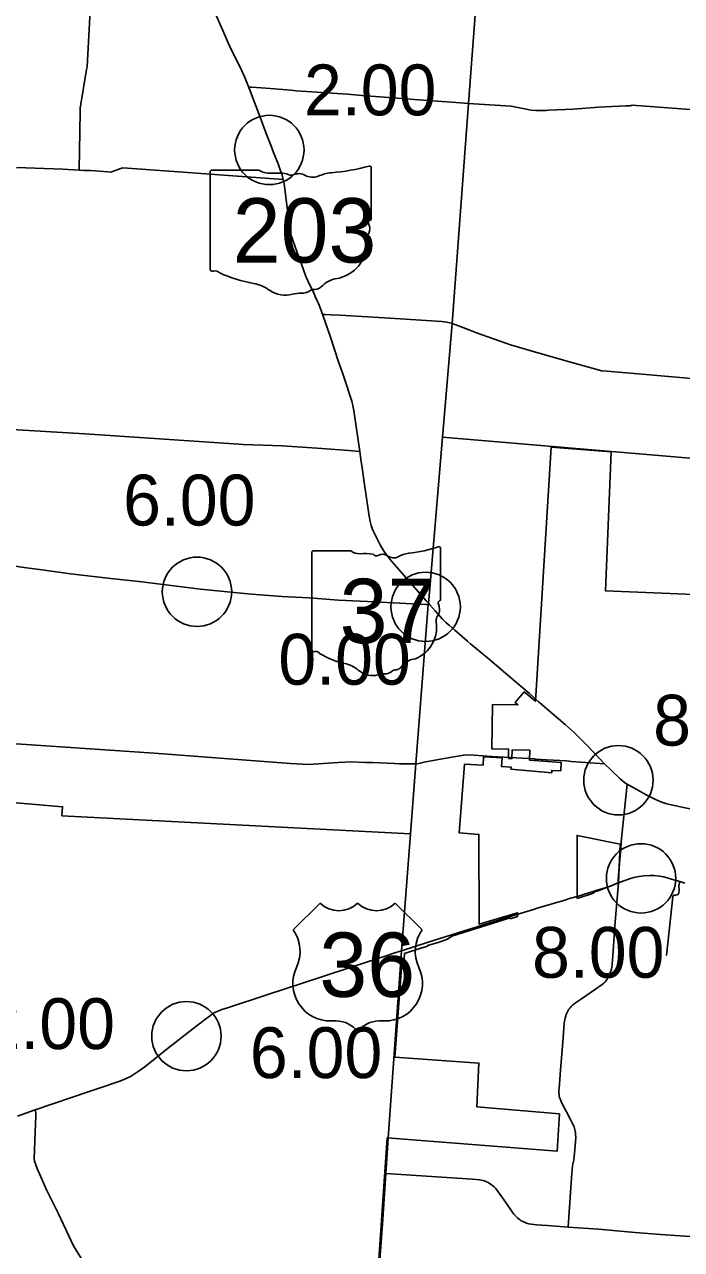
# Model space of a CAD drawing. Extents: x 1729596 to 1934326, y 644115 to 911751.
# Drawn here: x 1785492 to 1799698, y 831686 to 858198 of the extents above; entities that cross this region are included whole.
import ezdxf

# ---------------------------------------------------------------- set-up
doc = ezdxf.new("R2010")
doc.units = 0
for name, color, linetype in [('Default', 7, 'Continuous'), ('GM_X_City_Street', 7, 'Continuous'), ('GM_X_Corporation', 7, 'Continuous'), ('GM_X_County_Road', 7, 'Continuous'), ('GM_X_State_Route', 7, 'Continuous'), ('GM_X_State_Shield', 7, 'Continuous'), ('GM_X_Township', 7, 'Continuous'), ('GM_X_Township_Road', 7, 'Continuous'), ('GM_X_US_Route', 7, 'Continuous'), ('GM_X_US_Shield', 7, 'Continuous')]:
    doc.layers.add(name, color=color, linetype=linetype)

msp = doc.modelspace()

# ---------------------------------------------------------------- linework, layer by layer
at = {"layer": 'Default'}
for centre in [(1790786, 855482), (1789222, 845920), (1794166, 845595), (1798335, 841842), (1798823, 839718), (1788994, 836303)]:
    msp.add_circle(centre, 750, dxfattribs=at)
at = {"layer": 'GM_X_City_Street'}
for points in [[(1797209, 842260), (1797313, 842248), (1798035, 842200)], [(1798391, 840480), (1798393, 840510), (1798525, 841754)], [(1797247, 832172), (1797308, 833027), (1797327, 833333), (1797341, 833506), (1797367, 833630), (1797385, 833772), (1797411, 834102), (1797410, 834129), (1797409, 834165), (1797403, 834211), (1797397, 834244), (1797390, 834277), (1797383, 834312), (1797374, 834341), (1797357, 834387), (1797336, 834430), (1797307, 834485), (1797208, 834668), (1797135, 834807), (1797094, 834887), (1797073, 834944), (1797063, 834978), (1797055, 835013), (1797051, 835044), (1797048, 835076), (1797048, 835124), (1797051, 835173), (1797082, 835564), (1797140, 836270), (1797162, 836583), (1797170, 836630), (1797176, 836667), (1797183, 836695), (1797196, 836742), (1797207, 836777), (1797219, 836804), (1797233, 836833), (1797248, 836861), (1797265, 836886), (1797288, 836914), (1797313, 836944), (1797338, 836971), (1797374, 837003), (1797407, 837026), (1797534, 837113), (1797816, 837304), (1797982, 837420), (1798018, 837451), (1798045, 837481), (1798068, 837511), (1798088, 837537), (1798108, 837569), (1798132, 837611), (1798147, 837650), (1798166, 837697), (1798185, 837753), (1798193, 837803), (1798199, 837862), (1798219, 838143), (1798256, 838693), (1798334, 839621)], [(1798334, 839621), (1798331, 839671)], [(1799374, 838047), (1799488, 839118), (1799511, 839323), (1799525, 839347), (1799540, 839354), (1799586, 839357), (1799611, 839361), (1799640, 839398), (1799646, 839456), (1799643, 839557), (1799664, 839649)], [(1793120, 830695), (1793232, 832236), (1793303, 833333), (1793351, 834085)], [(1793303, 833333), (1795175, 833207), (1795258, 833200), (1795331, 833194), (1795377, 833186), (1795411, 833177), (1795450, 833165), (1795485, 833150), (1795520, 833133), (1795550, 833116), (1795584, 833095), (1795621, 833066), (1795649, 833041), (1795673, 833015), (1795735, 832935), (1795861, 832755), (1796037, 832503), (1796074, 832453), (1796109, 832412), (1796137, 832383), (1796162, 832362), (1796185, 832343), (1796207, 832326), (1796232, 832310), (1796267, 832291), (1796301, 832276), (1796344, 832258), (1796395, 832244), (1796451, 832232), (1796564, 832223), (1796677, 832214), (1796800, 832206), (1797247, 832172), (1797901, 832125), (1798456, 832073), (1798693, 832053), (1799244, 832014), (1800095, 831955)]]:
    msp.add_lwpolyline(points, dxfattribs=at)
at = {"layer": 'GM_X_Corporation'}
msp.add_lwpolyline([(1793093, 830632), (1793335, 834100), (1797009, 833813), (1797057, 834620), (1795274, 834775), (1795316, 835721), (1793499, 835852), (1793659, 837976), (1793698, 837973), (1793707, 838091), (1794085, 838213), (1794212, 838252), (1794209, 838262), (1794434, 838332), (1794637, 838403), (1794733, 838467), (1794733, 838467), (1795997, 838865), (1795996, 838844), (1796153, 838890), (1796155, 838973), (1795326, 838724), (1795319, 840669), (1794894, 840702), (1795009, 842190), (1795409, 842166), (1795420, 842348), (1795817, 842324), (1795804, 842142), (1796013, 842128), (1796009, 842085), (1796891, 842003), (1796893, 842053), (1797088, 842046), (1797094, 842227), (1796414, 842277), (1796416, 842493), (1796036, 842499), (1796033, 842307), (1795958, 842309), (1795961, 842515), (1795598, 842521), (1795613, 843484), (1796162, 843475), (1796105, 843523), (1796297, 843753), (1796540, 843550), (1796878, 849051), (1798177, 848946), (1798053, 845944), (1800661, 845836)], dxfattribs=at)
msp.add_lwpolyline([(1797441, 839284), (1797798, 839399), (1797801, 839422), (1797912, 839458), (1798198, 839567), (1798339, 839626), (1798371, 840459), (1797440, 840649)], close=True, dxfattribs=at)
at = {"layer": 'GM_X_County_Road'}
for points in [[(1786675, 855044), (1786697, 856311), (1786698, 856387), (1786835, 857221), (1786845, 857279), (1786936, 858914), (1786940, 858987), (1787642, 860408), (1787683, 860493), (1787941, 860759), (1788006, 860826), (1788012, 861039), (1788018, 861131), (1788033, 861371)], [(1785318, 855106), (1786321, 855070), (1786675, 855044), (1786776, 855041), (1786778, 855041)], [(1786778, 855041), (1786924, 855037), (1787292, 855007), (1787356, 855002), (1787555, 855074), (1787618, 855096), (1788721, 855019), (1789216, 854979), (1789701, 854941), (1790989, 854849), (1791087, 854843)], [(1793847, 840780), (1793954, 842199), (1794218, 845643)], [(1784027, 842716), (1788298, 842429), (1791241, 842207), (1791633, 842186), (1792271, 842228), (1792567, 842237), (1792853, 842229), (1793017, 842224), (1793496, 842204), (1793598, 842199), (1793716, 842194), (1793856, 842196), (1793901, 842196), (1793954, 842199)], [(1793954, 842199), (1794020, 842207), (1794133, 842230), (1794444, 842288), (1794735, 842342), (1794989, 842386), (1795095, 842389), (1795206, 842386), (1795597, 842359), (1796522, 842302), (1796538, 842301)], [(1796538, 842301), (1796781, 842284), (1797209, 842260)], [(1793647, 838152), (1793839, 840685), (1793847, 840780)], [(1798331, 839671), (1798329, 839693), (1798369, 840209), (1798391, 840480)], [(1793351, 834085), (1793352, 834099), (1793647, 838152)]]:
    msp.add_lwpolyline(points, dxfattribs=at)
at = {"layer": 'GM_X_State_Route'}
for points in [[(1794187, 845719), (1793434, 846579), (1793324, 846710), (1793274, 846777), (1793187, 846924), (1793100, 847093), (1793045, 847210), (1793027, 847252), (1793013, 847289), (1792991, 847355), (1792967, 847443), (1792946, 847558), (1792850, 848193), (1792784, 848652), (1792773, 848731), (1792740, 848959), (1792628, 849742), (1792619, 849803), (1792592, 849950), (1792568, 850047), (1792530, 850174), (1792441, 850445), (1792367, 850662), (1792285, 850899), (1792105, 851429), (1791940, 851905), (1791877, 852084), (1791846, 852163), (1791822, 852220), (1791780, 852313), (1791755, 852366), (1791702, 852474), (1791642, 852598), (1791571, 852765), (1791525, 852890), (1791444, 853113), (1791397, 853241), (1791277, 853572), (1791258, 853631), (1791244, 853685), (1791226, 853784), (1791205, 853939), (1791111, 854702), (1791100, 854784), (1791087, 854843), (1791073, 854900), (1791061, 854942), (1791021, 855052), (1790974, 855179), (1790879, 855426), (1790817, 855588), (1790721, 855839), (1790647, 856032), (1790607, 856138), (1790378, 856737), (1790341, 856833), (1790254, 857050), (1790190, 857197), (1790044, 857488), (1789945, 857688), (1789872, 857851), (1789828, 857951), (1789562, 858562)], [(1782747, 846479), (1782794, 846480), (1783183, 846484), (1783377, 846485), (1783923, 846492), (1784269, 846503), (1784713, 846520), (1784920, 846517), (1785189, 846487), (1785532, 846441), (1785928, 846388), (1786488, 846310), (1787292, 846217), (1788027, 846133), (1788780, 846042), (1789296, 845980), (1789805, 845926), (1790403, 845872), (1791058, 845819), (1791646, 845786), (1792283, 845741), (1792907, 845707), (1794165, 845645)], [(1794256, 845640), (1794225, 845677), (1794187, 845719)], [(1794165, 845645), (1794218, 845643), (1794256, 845640)], [(1794256, 845640), (1794372, 845506), (1794532, 845328), (1794610, 845252), (1794673, 845195), (1794795, 845090), (1795070, 844854), (1795139, 844795), (1795501, 844493), (1796141, 843947), (1796409, 843716), (1796609, 843541)], [(1796609, 843541), (1796627, 843525), (1796897, 843295), (1796897, 843295)], [(1796897, 843295), (1797184, 843049), (1797375, 842873), (1797459, 842793), (1797671, 842582), (1798035, 842200), (1798181, 842051), (1798372, 841875), (1798417, 841833), (1798475, 841788), (1798525, 841754), (1798715, 841646), (1798952, 841516), (1799123, 841431), (1799251, 841372), (1799337, 841343), (1799378, 841331), (1799477, 841307), (1799775, 841246), (1800109, 841182)]]:
    msp.add_lwpolyline(points, dxfattribs=at)
at = {"layer": 'GM_X_State_Shield'}
for p, q in [((1789509, 855011), (1789509, 852897)), ((1789509, 855011), (1789509, 852897)), ((1790562, 855047), (1789543, 855047)), ((1790562, 855047), (1789543, 855047)), ((1792989, 853994), (1792989, 855099)), ((1792989, 853994), (1792989, 855099)), ((1792989, 853994), (1792989, 853994)), ((1792989, 853994), (1792989, 853994)), ((1792549, 846810), (1791733, 846810)), ((1792549, 846810), (1791733, 846810)), ((1794490, 845757), (1794490, 846862)), ((1794490, 845757), (1794490, 846862)), ((1791706, 846774), (1791706, 844660)), ((1791706, 846774), (1791706, 844660)), ((1794490, 845757), (1794490, 845757)), ((1794490, 845757), (1794490, 845757))]:
    msp.add_line(p, q, dxfattribs=at)
for centre, radius, start, end in [((1791738, 846778), 32.3, 98.1301, 188.1301), ((1791738, 846778), 32.3, 98.1301, 188.1301), ((1792743, 847055), 313, 231.6195, 271.1119), ((1792743, 847055), 313, 231.6195, 271.1119), ((1793498, 849691), 2953, 275.8445, 288.9065), ((1793498, 849691), 2953, 275.8445, 288.9065), ((1794459, 846867), 31, 351.8621, 97.738), ((1794459, 846867), 31, 351.8621, 97.738), ((1792846, 845624), 1123, 80.4867, 94.9883), ((1792846, 845624), 1123, 80.4867, 94.9883), ((1793101, 846789), 90.3, 219.7921, 297.1024), ((1793101, 846789), 90.3, 219.7921, 297.1024), ((1793234, 846545), 188, 54.4667, 119.1411), ((1793234, 846545), 188, 54.4667, 119.1411), ((1793476, 846880), 226, 233.8562, 294.8282), ((1793476, 846880), 226, 233.8562, 294.8282), ((1793875, 846165), 594, 97.3462, 120.7689), ((1793875, 846165), 594, 97.3462, 120.7689), ((1794483, 845676), 48, 107.944, 210.337), ((1794483, 845676), 48, 107.944, 210.337), ((1794457, 845753), 33.2, 289.6038, 7.7341), ((1794457, 845753), 33.2, 289.6038, 7.7341), ((1794178, 845536), 288, 340.033, 23.6496), ((1794178, 845536), 288, 340.033, 23.6496), ((1793664, 845154), 739, 292.3089, 8.9858), ((1793664, 845154), 739, 292.3089, 8.9858), ((1794601, 845294), 210, 136.8065, 186.9296), ((1794601, 845294), 210, 136.8065, 186.9296), ((1791738, 844656), 32.5, 171.9584, 258.3066), ((1791738, 844656), 32.5, 171.9584, 258.3066), ((1791743, 844872), 248, 267.339, 280.6039), ((1791743, 844872), 248, 267.339, 280.6039), ((1791794, 844539), 89.5, 29.7484, 93.2717), ((1791794, 844539), 89.5, 29.7484, 93.2717), ((1792924, 846437), 2132, 240.4129, 257.1985), ((1792924, 846437), 2132, 240.4129, 257.1985), ((1793975, 844067), 404, 94.4031, 142.5768), ((1793975, 844067), 404, 94.4031, 142.5768), ((1792288, 843711), 667, 47.1842, 75.836), ((1792288, 843711), 667, 47.1842, 75.836), ((1793010, 844528), 423, 230.7004, 286.2918), ((1793010, 844528), 423, 230.7004, 286.2918), ((1793255, 843797), 348, 85.6951, 111.2099), ((1793255, 843797), 348, 85.6951, 111.2099), ((1793286, 844370), 226, 268.777, 315.5493), ((1793286, 844370), 226, 268.777, 315.5493), ((1793490, 844165), 63.5, 65.7517, 132.6484), ((1793490, 844165), 63.5, 65.7517, 132.6484), ((1793463, 844456), 239, 282.8732, 323.2771), ((1793463, 844456), 239, 282.8732, 323.2771)]:
    msp.add_arc(centre, radius, start, end, dxfattribs=at)
for centre, major_axis, start_param, end_param in [((1789548, 855015), (40.3, 0), 1.712693, 3.28349), ((1789548, 855015), (40.3, 0), 1.712693, 3.28349), ((1790805, 855292), (391, 0), 4.042523, 4.731795), ((1790805, 855292), (391, 0), 4.042523, 4.731795), ((1791749, 857928), (3691, 0), 4.814394, 5.042369), ((1791749, 857928), (3691, 0), 4.814394, 5.042369), ((1792950, 855104), (38.7, 0), 6.141152, 7.989035), ((1792950, 855104), (38.7, 0), 6.141152, 7.989035), ((1790935, 853860), (1404, 0), 1.404758, 1.657858), ((1790935, 853860), (1404, 0), 1.404758, 1.657858), ((1791253, 855026), (113, 0), 3.836095, 5.185415), ((1791253, 855026), (113, 0), 3.836095, 5.185415), ((1791419, 854782), (235, 0), 0.950623, 2.079405), ((1791419, 854782), (235, 0), 0.950623, 2.079405), ((1791722, 855117), (282, 0), 4.081561, 5.145723), ((1791722, 855117), (282, 0), 4.081561, 5.145723), ((1792220, 854401), (743, 0), 1.699011, 2.107814), ((1792220, 854401), (743, 0), 1.699011, 2.107814), ((1792980, 853913), (60, 0), 1.883978, 3.671073), ((1792980, 853913), (60, 0), 1.883978, 3.671073), ((1792948, 853990), (41.5, 0), 5.05454, 6.418171), ((1792948, 853990), (41.5, 0), 5.05454, 6.418171), ((1793128, 853531), (262, 0), 2.387724, 3.262537), ((1793128, 853531), (262, 0), 2.387724, 3.262537), ((1792599, 853773), (360, 0), 5.934695, 6.695948), ((1792599, 853773), (360, 0), 5.934695, 6.695948), ((1791956, 853391), (923, 0), 5.101752, 6.440018), ((1791956, 853391), (923, 0), 5.101752, 6.440018), ((1789549, 852893), (40.7, 0), 3.00124, 4.508301), ((1789549, 852893), (40.7, 0), 3.00124, 4.508301), ((1789555, 853109), (310, 0), 4.665946, 4.897461), ((1789555, 853109), (310, 0), 4.665946, 4.897461), ((1789619, 852775), (112, 0), 0.519207, 1.627899), ((1789619, 852775), (112, 0), 0.519207, 1.627899), ((1791032, 854674), (2665, 0), 4.195997, 4.488961), ((1791032, 854674), (2665, 0), 4.195997, 4.488961), ((1792345, 852304), (506, 0), 1.647645, 2.488434), ((1792345, 852304), (506, 0), 1.647645, 2.488434), ((1790237, 851948), (834, 0), 0.823519, 1.323587), ((1790237, 851948), (834, 0), 0.823519, 1.323587), ((1791139, 852765), (529, 0), 4.026481, 4.996735), ((1791139, 852765), (529, 0), 4.026481, 4.996735), ((1791445, 852034), (435, 0), 1.495662, 1.94098), ((1791445, 852034), (435, 0), 1.495662, 1.94098), ((1791483, 852607), (282, 0), 4.691044, 5.507374), ((1791483, 852607), (282, 0), 4.691044, 5.507374), ((1791739, 852402), (79.4, 0), 1.147584, 2.315152), ((1791739, 852402), (79.4, 0), 1.147584, 2.315152), ((1791705, 852692), (298, 0), 4.937069, 5.64225), ((1791705, 852692), (298, 0), 4.937069, 5.64225)]:
    msp.add_ellipse(centre, major_axis=major_axis, ratio=0.8, start_param=start_param, end_param=end_param, dxfattribs=at)
at = {"layer": 'GM_X_Township'}
for points in [[(1795247, 858499), (1795090, 856488), (1794738, 851729), (1794528, 849265), (1794250, 845913), (1794225, 845677), (1794218, 845643), (1793954, 842199), (1793839, 840685), (1786300, 841075), (1786314, 841270), (1782391, 841606)], [(1794528, 849265), (1800736, 848740), (1801113, 848728), (1805038, 848430), (1809012, 848241), (1810328, 848152), (1816586, 847751), (1820950, 847472)], [(1792915, 827502), (1793120, 830695), (1793232, 832236), (1793303, 833333), (1793352, 834099), (1793647, 838152), (1793839, 840685)]]:
    msp.add_lwpolyline(points, dxfattribs=at)
at = {"layer": 'GM_X_Township_Road'}
for points in [[(1795090, 856488), (1795247, 858499), (1795248, 858510)], [(1790341, 856833), (1790361, 856840), (1790407, 856844), (1790813, 856811), (1791251, 856773), (1791363, 856765), (1792476, 856688), (1792792, 856660), (1793270, 856623), (1794021, 856567), (1794727, 856514), (1795090, 856488)], [(1795090, 856488), (1796016, 856428), (1796449, 856346), (1796551, 856339), (1796604, 856337), (1796665, 856335), (1796771, 856339), (1796829, 856341), (1797357, 856367), (1797448, 856371), (1797816, 856403), (1797914, 856411), (1798495, 856434), (1798591, 856437), (1798633, 856451), (1800371, 856321), (1800474, 856313), (1801054, 856281), (1801112, 856277), (1801481, 856249), (1801549, 856244)], [(1791940, 851905), (1791969, 851918), (1791991, 851922), (1792120, 851917), (1792308, 851904), (1793274, 851846), (1794516, 851767), (1794619, 851757), (1794724, 851732)], [(1794724, 851732), (1794738, 851729), (1794935, 851656), (1795122, 851581), (1795265, 851527), (1796002, 851268), (1796641, 851079), (1797379, 850870), (1797893, 850723), (1797966, 850705), (1798085, 850695), (1798763, 850635), (1800156, 850514), (1800763, 850469), (1801182, 850439), (1801250, 850449)], [(1784612, 849472), (1786799, 849340), (1790129, 849115), (1790221, 849109), (1791065, 849081), (1791820, 849028), (1792506, 848978), (1792740, 848959)], [(1788621, 827994), (1788650, 828063), (1788726, 828178), (1788739, 828252), (1788721, 828512), (1788707, 828711), (1788718, 828879), (1788680, 829037), (1788510, 829354), (1788376, 829562), (1787776, 830325), (1787442, 830711), (1787118, 831016), (1786817, 831334), (1786550, 831763), (1786230, 832458), (1785968, 832975), (1785767, 833439), (1785710, 833597), (1785701, 833646), (1785722, 834226), (1785735, 834569), (1785736, 834651), (1785723, 834708)]]:
    msp.add_lwpolyline(points, dxfattribs=at)
at = {"layer": 'GM_X_US_Route'}
for points in [[(1797279, 839280), (1797440, 839329), (1797949, 839483), (1798026, 839508), (1798154, 839553), (1798334, 839621)], [(1798334, 839621), (1798449, 839665), (1798596, 839716), (1798693, 839742), (1798786, 839760), (1798883, 839772), (1799014, 839778), (1799098, 839777), (1799221, 839764), (1799313, 839748), (1799413, 839724), (1799529, 839690), (1799664, 839649), (1799768, 839617)], [(1796520, 839053), (1796580, 839071), (1797177, 839250)], [(1797177, 839250), (1797279, 839280)], [(1794201, 838327), (1794977, 838574), (1796065, 838914)], [(1796065, 838914), (1796113, 838930), (1796115, 838930)], [(1796115, 838930), (1796520, 839053)], [(1793596, 838135), (1793647, 838152), (1794201, 838327)], [(1785341, 834572), (1785723, 834708), (1786913, 835110), (1787149, 835192), (1787535, 835324), (1787660, 835373), (1787802, 835441), (1787953, 835536), (1788092, 835640), (1788316, 835821), (1788577, 836027), (1789200, 836511), (1789464, 836715), (1789512, 836752), (1789559, 836786), (1789581, 836800), (1789608, 836815), (1789657, 836839), (1789708, 836860), (1789760, 836879), (1789880, 836917), (1790713, 837188), (1791944, 837592), (1792535, 837787), (1793152, 837991), (1793294, 838037)], [(1793294, 838037), (1793503, 838105), (1793596, 838135)]]:
    msp.add_lwpolyline(points, dxfattribs=at)
at = {"layer": 'GM_X_US_Shield'}
for p, q in [((1791884, 839184), (1791304, 838604)), ((1791884, 839184), (1791304, 838604)), ((1794088, 838604), (1793508, 839184)), ((1794088, 838604), (1793508, 839184)), ((1792116, 836632), (1792232, 836632)), ((1792116, 836632), (1792232, 836632)), ((1793160, 836632), (1793276, 836632)), ((1793160, 836632), (1793276, 836632))]:
    msp.add_line(p, q, dxfattribs=at)
for centre, radius, start, end in [((1792290, 839599), 580, 225.573, 314.427), ((1792290, 839599), 580, 225.573, 314.427), ((1793102, 839599), 580, 225.573, 314.427), ((1793102, 839599), 580, 225.573, 314.427), ((1790639, 838139), 812, 334.5471, 35.0009), ((1790639, 838139), 812, 334.5471, 35.0009), ((1794753, 838139), 812, 144.9991, 205.4529), ((1794753, 838139), 812, 144.9991, 205.4529), ((1792107, 837444), 812, 154.8319, 270.6383), ((1792107, 837444), 812, 154.8319, 270.6383), ((1793285, 837444), 812, 269.3617, 25.1681), ((1793285, 837444), 812, 269.3617, 25.1681), ((1792232, 836052), 580, 36.8699, 90), ((1792232, 836052), 580, 36.8699, 90), ((1793160, 836052), 580, 90, 143.1301), ((1793160, 836052), 580, 90, 143.1301)]:
    msp.add_arc(centre, radius, start, end, dxfattribs=at)

# ---------------------------------------------------------------- texts
at = {"layer": 'Default'}
for s, p in [('2.00', (1791536, 856232)), ('6.00', (1787624, 847355)), ('0.00', (1790981, 843910)), ('8.00', (1799085, 842592)), ('8.00', (1796467, 837567)), ('12.00', (1783768, 836024)), ('6.00', (1790365, 835396))]:
    msp.add_text(s, height=1100, dxfattribs=at).set_placement(p)
at = {"layer": 'GM_X_State_Shield'}
for s, p in [('203', (1789994, 853046)), ('203', (1789994, 853046)), ('37', (1792306, 844810)), ('37', (1792306, 844810))]:
    msp.add_text(s, height=1392.2, dxfattribs=at).set_placement(p)
at = {"layer": 'GM_X_US_Shield'}
msp.add_text('36', height=1392.2, dxfattribs=at).set_placement((1791868, 837154))
msp.add_text('36', height=1392.2, dxfattribs=at).set_placement((1791868, 837154))

doc.saveas('drawing.dxf')
